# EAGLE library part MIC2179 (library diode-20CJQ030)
Micrel's MIC2179 1.5A synchronous buck regulator General Description: The Micrel MIC2179 is a 200kHz synchronous buck (stepdown) switching regulator designed for high-efficiency, batterypowered applications. The MIC2179 operates from a 4.5V to 16.5V input and features internal power MOSFETs that can supply up to 1.5A output current. It can operate with a maximum duty cycle of 100% for use in low-dropout conditions. It also features a shutdown mode that reduces quiescent current to less than 5µA. The MIC2179 achieves high efficiency over a wide output current range by operating in either PWM or skip mode. The operating mode is externally selected, typically by an intelligent system, which chooses the appropriate mode according to operating conditions, efficiency, and noise requirements. The switching frequency is preset to 200kHz and can be synchronized to an external clock signal of up to 300kHz. The MIC2179 uses current-mode control with internal current sensing. Current-mode control provides superior line regulation and makes the regulator control loop easy to compensate. The output is protected with pulse-by-pulse current limiting and thermal shutdown. Undervoltage lockout turns the output off when the input voltage is less than 4.5V. The MIC2179 and is packaged in a 20-lead SSOP package with an operating temperature range of -40°C to +85°C. Features: 4.5V to 16.5V input voltage range Dual-mode operation for high efficiency (up to 96%) PWM mode for > 150mA load current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
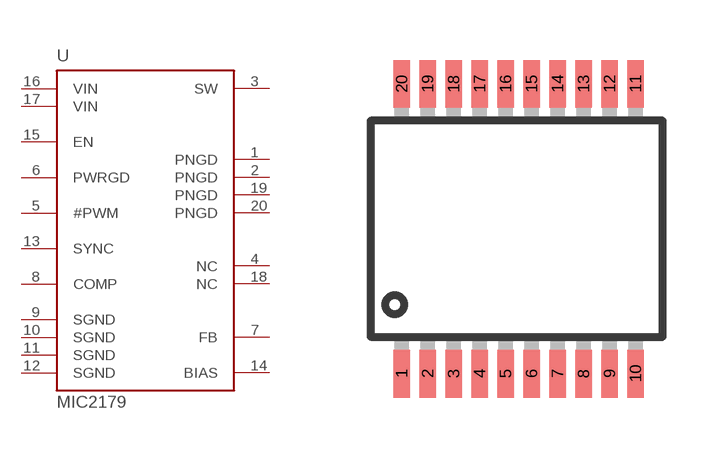
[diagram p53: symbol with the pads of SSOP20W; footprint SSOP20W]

Designator prefix U

## MIC2179SSOP20W  [SSOP20W]
1  PNGD  pwr
2  PNGD  pwr
3  SW  out
4  NC  nc
5  #PWM
6  PWRGD  out
7  FB
8  COMP  out
9  SGND  pwr
10  SGND  pwr
11  SGND  pwr
12  SGND  pwr
13  SYNC  in
14  BIAS
15  EN  in
16  VIN  pwr
17  VIN  pwr
18  NC  nc
19  PNGD  pwr
20  PNGD  pwr

## Footprint SSOP20W (pad centres in mm)
smd 0.42 x 1.2: 1 -2.925,-3.625; 2 -2.275,-3.625; 3 -1.625,-3.625; 4 -0.975,-3.625; 5 -0.325,-3.625; 6 0.325,-3.625; 7 0.975,-3.625; 8 1.625,-3.625; 9 2.275,-3.625; 10 2.925,-3.625; 11 2.925,3.625; 12 2.275,3.625; 13 1.625,3.625; 14 0.975,3.625; 15 0.325,3.625; 16 -0.325,3.625; 17 -0.975,3.625; 18 -1.625,3.625; 19 -2.275,3.625; 20 -2.925,3.625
